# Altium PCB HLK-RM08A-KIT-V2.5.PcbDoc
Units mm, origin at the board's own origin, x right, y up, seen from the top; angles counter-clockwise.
Board outline 90 x 99 mm, 2 copper layers (Top Layer, Bottom Layer); 69 components, 103 nets, 378 pads, 257 vias.
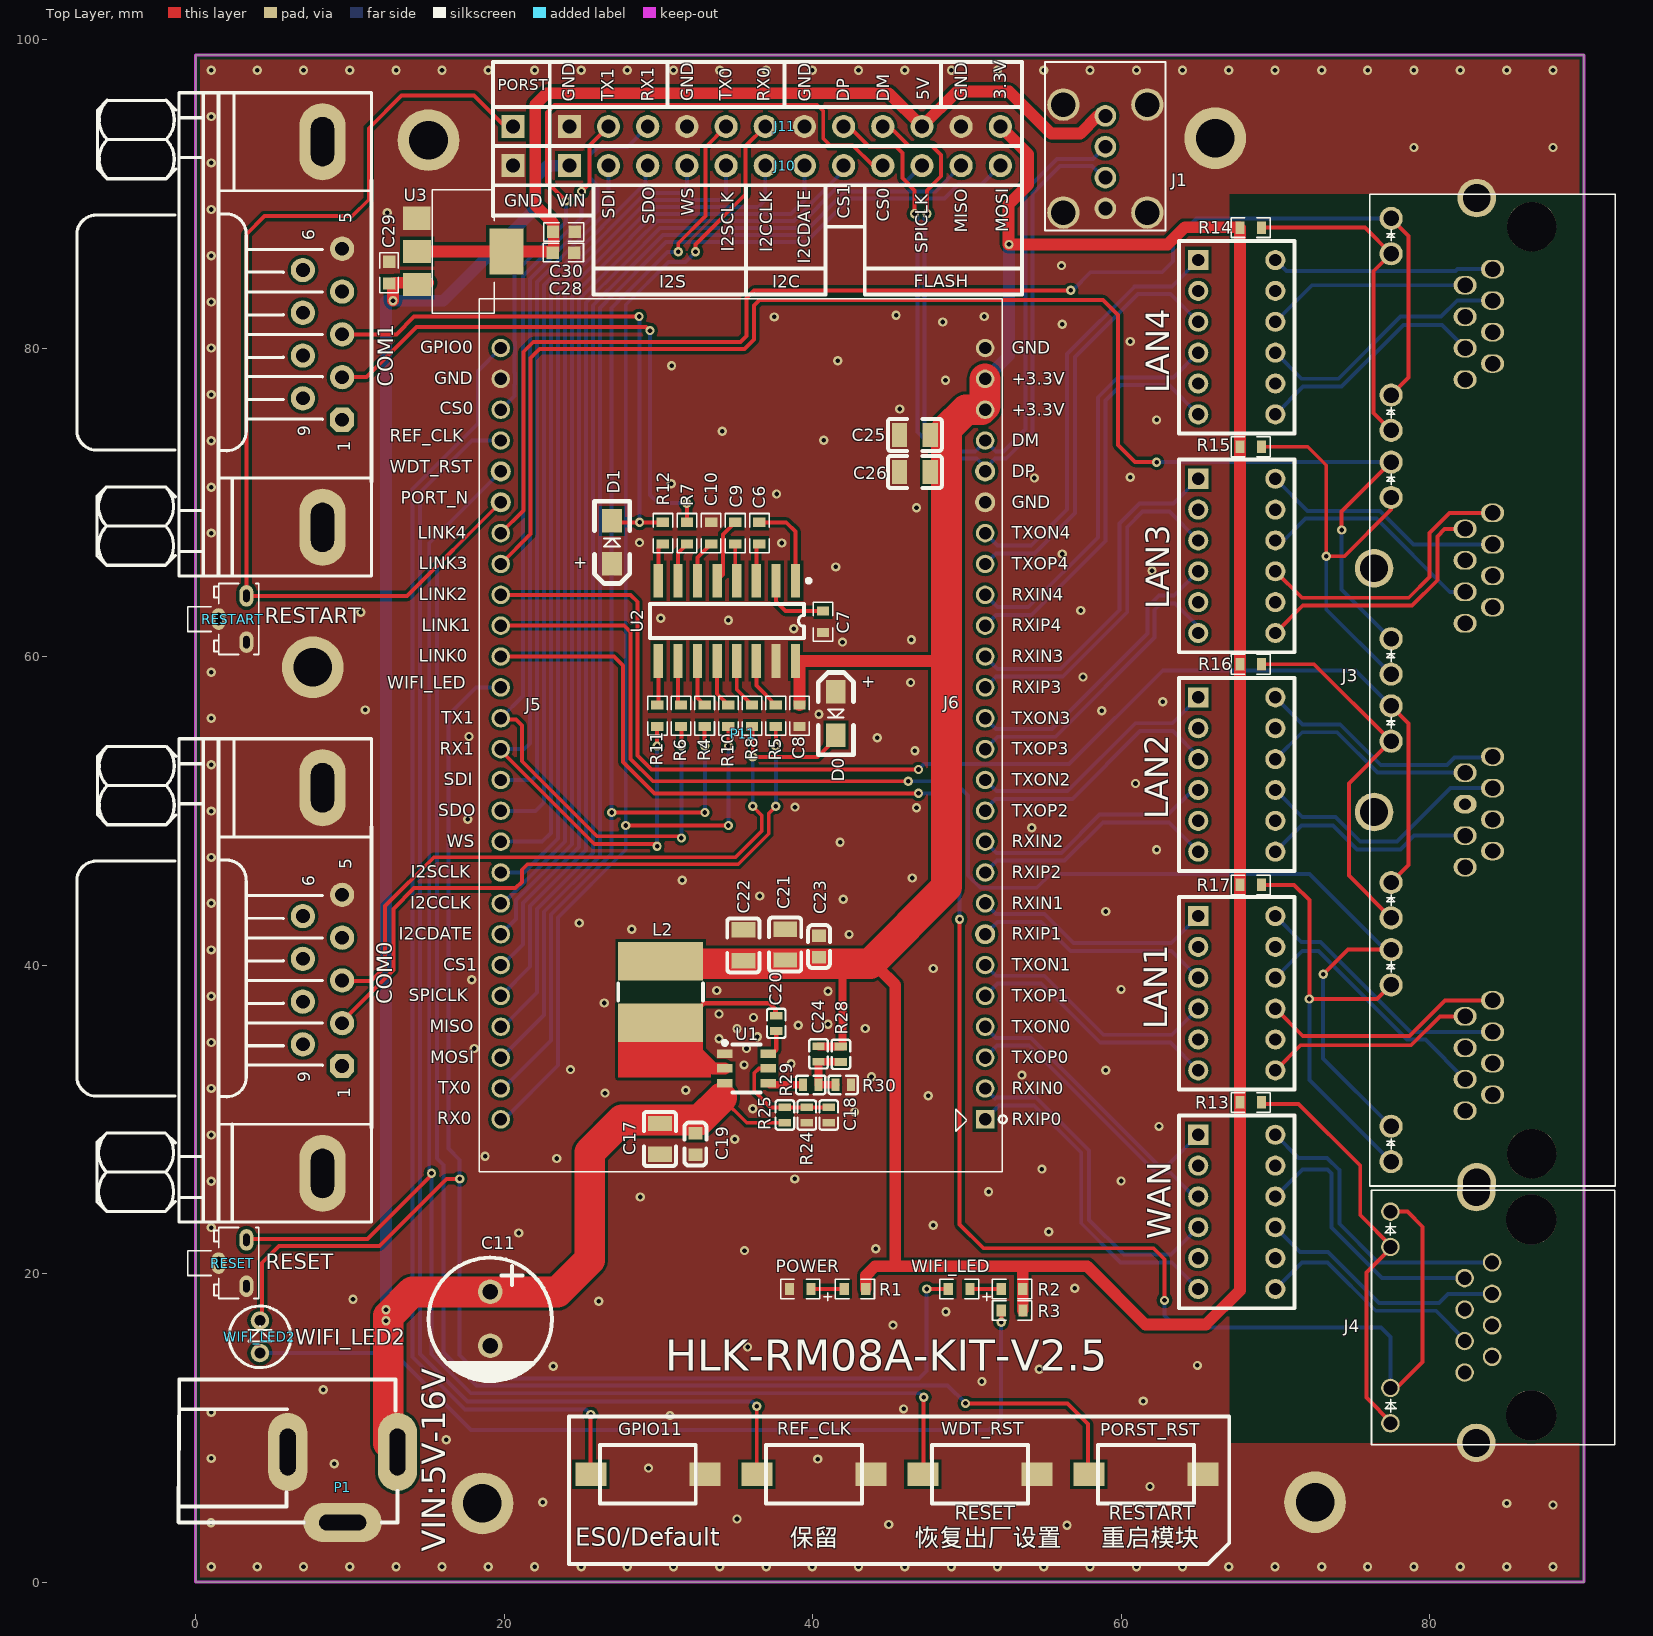
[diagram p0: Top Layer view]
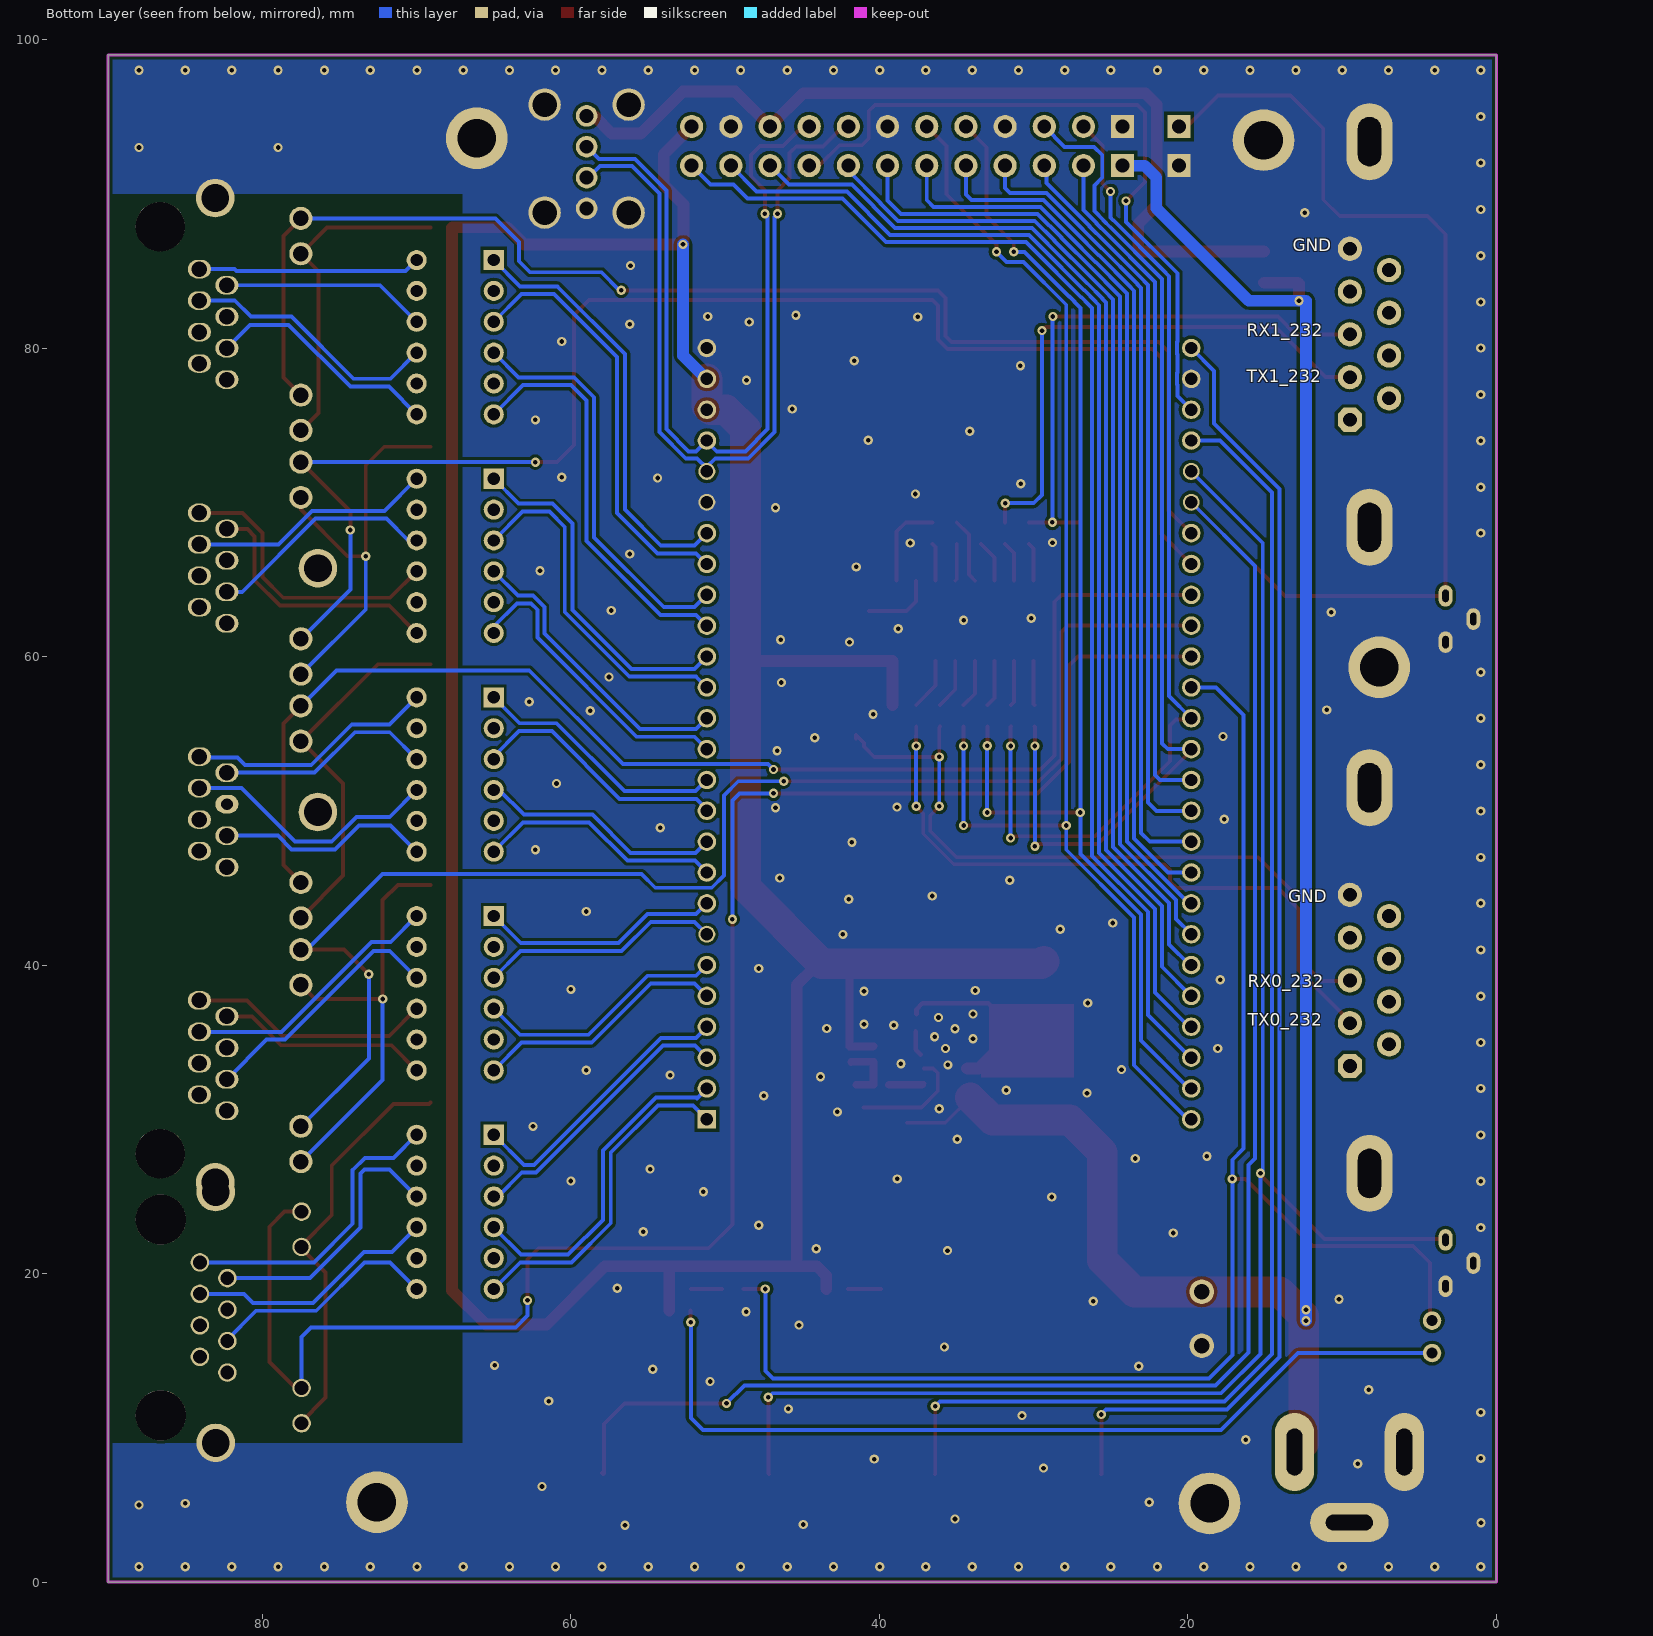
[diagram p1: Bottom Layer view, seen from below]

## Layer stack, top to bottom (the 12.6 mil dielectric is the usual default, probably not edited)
Top Layer: signal copper 0.0356
Dielectric: dielectric 0.32, FR-4, Dk 4.8
Bottom Layer: signal copper 0.0356

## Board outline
0,0 90,0 90,99 0,99

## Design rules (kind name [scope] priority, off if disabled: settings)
Clearance keepout [All] p1: gap=0.2
Clearance router [InNet('GND')] p2: gap=0.2
PlaneConnect [All] p1: planeconnectstyle=Direct reliefexpansion=0.508 reliefentries=4 reliefconductorwidth=0.254 reliefairgap=0.254
PolygonConnect [All] p1: connectstyle=Direct reliefconductorwidth=0.254 reliefentries=4 polygonreliefangle="90 Angle"
RoomDefinition HLK-RM08A-KIT-V2.5 [InComponentClass('HLK-RM08A-KIT-V2.5')] p1: confinementstyle=ConfineIn formatcopy=TRUE lockcomponents=FALSE outline -44.961,-21.523 5.839,-21.523 5.839,3.877 -44.961,3.877
RoutingVias [All] p1: holewidth=0.4 width=0.8 viastyle="Through Hole" minholewidth=0.305 minwidth=0.711 maxholewidth=0.711 maxwidth=1.27
SilkscreenOverComponentPads [IsPad] p1: minsilkscreentomaskgap=0.254
SolderMaskExpansion [All] p1: expansion=0.102
TestPointUsage [All] p1: valid=0 allowmultiple=FALSE
Testpoint [(IsPad And (OnTopLayer Or OnBottomLayer))] p1: side=3 testpointundercomponent=TRUE minsize=1.016 maxsize=2.54 preferedsize=1.524 minholesize=0 maxholesize=1.016 preferedholesize=0.813 testpointgrid=0.025 style=297 order=0-112345678
Width [All] p1: maxlimit=3 minlimit=0.18 preferedwidth=0.2
22 further rules are at their usual default settings.

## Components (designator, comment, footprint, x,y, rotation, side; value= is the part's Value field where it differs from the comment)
C6 "0.1uF/6.3V" 0603#1 36.55,68.001 r90 top
C7 "0.1uF/6.3V" 0603#1 40.671,62.254 r270 top
C8 "0.1uF/6.3V" 0603#1 39.147,56.158 r270 top
C9 "0.1uF/6.3V" 0603#1 34.986,68.001 r270 top
C10 "0.1uF/6.3V" 0603#1 33.422,68.001 r270 top
C11 "470uF 25V" "1000uF 8*12 电解电容" 19.101,17.069 r270 top
C17 "10uF/25V" 0805 30.099,28.727 r90 top
C18 "NC" 0402 41.046,30.277 r90 top
C19 "0.1uF/25V" 0603#2 32.41,28.397 r90 top
C20 "1uF/25V" 0402 37.643,36.22 r270 top
C21 "22uF/6.3V" 0805 38.227,41.326 r270 top
C22 "22uF/6.3V" 0805 35.509,41.275 r270 top
C23 "0.1uF/6.3V" 0603#2 40.411,41.199 r270 top
C24 "NC" 0402 40.386,34.239 r270 top
C25 "22uF/6.3V" 0805 46.634,74.371 r0 top
C26 "22uF/6.3V" 0805 46.634,71.958 r0 top
C28 "0.1uF/6.3V" 0603#3 23.851,86.182 r0 top
C29 "22uF/25V" 0603#3 12.548,84.887 r90 top
C30 "10uF/6.3V" 0603#3 23.876,87.528 r0 top
COM0 "DB9" DB9s 9.5,44.551 r90 top
COM1 "DB9" DB9s 9.5,86.432 r90 top locked
D0 "ZMM5V1" 1005D 41.513,57.701 r270 top
D1 "ZMM5V1" 1005D 27,66 r90 top
GPIO11 "SW-PB" SWITCH 29.185,6.992 r180 top
J1 "USB" USB/4P/P2.0/DIP/R/F/SUA-110VB-B2N 58.979,95.047 r90 top
J3 "RJ45-4" RJ45-4-LED 82.3,46.35 r90 top
J4 "RJ45" RJ45-1-LED 84.048,20.725 r90 top
J10 "2.54*16" HDR1X12 24.232,91.821 r0 top
J11 "2.54*16" HDR1X12 24.232,94.361 r0 top
L2 "6.8uH" "4.7uH SMD,5.8x5.2x4.5mm" 30.15,38.252 r90 top
LAN1 "TF-1016DG" tf-1016dg 65,43.175 r270 top locked
LAN2 "TF-1016DG" tf-1016dg 65,57.35 r270 top locked
LAN3 "TF-1016DG" tf-1016dg 65,71.525 r270 top locked
LAN4 "TF-1016DG" tf-1016dg 65,85.7 r270 top locked
P1 "PWR2.5" POWER_STK1 9.534,8.941 r0 top locked
P11 "7688A" RM08K_52pin 51.186,30 r90 top locked
PORST_RST "SW-PB" SWITCH 61.471,6.992 r180 top
POWER "" 0603LED 39.2,19.001 r180 top
R1 "1K" 0603#1 42.745,19.001 r0 top
R2 "1K" 0603#1 52.931,19.001 r0 top
R3 "1K" 0603#1 52.934,17.602 r0 top
R4 "0R" 0603#1 33.007,56.158 r90 top
R5 "0R" 0603#1 37.612,56.158 r270 top
R6 "0R" 0603#1 31.472,56.158 r90 top
R7 "0R" 0603#1 31.858,68.001 r90 top
R8 "0R" 0603#1 36.077,56.158 r270 top
R10 "0R" 0603#1 34.542,56.158 r90 top
R11 "0R" 0603#1 29.937,56.158 r90 top
R12 "0R" 0603#1 30.293,68.001 r90 top
R13 "1K" 0603#1 68.4,31.1 r180 top
R14 "1K" 0603#1 68.4,87.8 r180 top
R15 "1K" 0603#1 68.4,73.6 r180 top
R16 "1K" 0603#1 68.4,59.5 r180 top
R17 "1K" 0603#1 68.4,45.2 r180 top
R24 "NC" 0402 39.624,30.277 r90 top
R25 "100K" 0402 38.202,30.277 r270 top
R28 "6.2K/1%" 0402 41.834,34.214 r90 top
R29 "1K" 0402 39.878,32.233 r0 top
R30 "2K/1%" 0402 41.986,32.233 r180 top
REF_CLK "SW-PB" SWITCH 39.947,6.992 r180 top
RESET "SW-PB" K5 1.5,20.682 r180 top
RESTART "SW-PB" K5 1.5,62.432 r180 top (schematic designator CS2)
U1 "MP1470" MP1470 35.712,33.299 r270 top
U2 "SP3232" MAX3232 29.495,63.778 r0 top
U3 "AMS1117-5" AMS1117 17.247,86.258 r270 top
WAN "TF-1016DG" tf-1016dg 65,29 r270 top locked
WDT_RST "SW-PB" SWITCH 50.709,6.992 r180 top
WIFI_LED "" 0603LED 49.5,19.001 r180 top
WIFI_LED2 "" LED0.2 4.175,14.85 r90 top

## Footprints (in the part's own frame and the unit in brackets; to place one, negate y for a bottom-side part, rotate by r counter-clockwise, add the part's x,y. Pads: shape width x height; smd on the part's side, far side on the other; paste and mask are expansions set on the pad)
"4.7uH SMD,5.8x5.2x4.5mm" [mm] "SMD,5.8x5.2x4.5mm"
  rect 2.5x5.5 smd: 1(-2,0) 2(2,0)
  silkscreen extent -0.55,-2.75 0.55,2.75
0402 [mm]
  rect 0.5x0.8 smd: 1(-0.5,0) 2(0.5,0)
  silkscreen extent -0.95,-0.6 0.95,0.6
0603#1 [mm]
  rect 0.6x0.8 smd: 1(-0.7,0) 2(0.7,0)
  silkscreen extent -1.27,-0.64 1.27,0.64
0603#2 [mm]
  rect 0.8x0.9 smd: 1(-0.7,0) 2(0.7,0)
  silkscreen extent -1.4,-0.7 1.4,0.72
0603#3 [mm]
  rect 0.8x0.8 smd: 1(-0.7,0) 2(0.7,0)
  silkscreen extent -1.3,-0.6 1.3,0.6
0603LED [mm]
  rect 0.6x0.8 smd: 1(-0.7,0) 2(0.7,0)
  silkscreen extent -2.03,-0.64 1.27,0.76
0805 [mm]
  rect 1x1.55 smd: 1(-1,0) 2(1,0)
  silkscreen extent -1.75,-1.04 1.75,1.04
"1000uF 8*12 电解电容" [mm]
  round 1.6 hole 1: 1(-1.75,0) 2(1.75,0)
  silkscreen extent -3.96,-4 4.04,4
1005D [mil]
  rect 60x50 smd: 1(0,0) 2(110,0)
  silkscreen extent -50,-45 160,45
AMS1117 [mm]
  rect 1.5x1.8 smd: 1(-2.153,-2.905) 2(0.003,-2.884) 3(2.153,-2.884)
  rect 3x2.2 smd: 2(0,2.905)
  silkscreen extent -4,-1.89 4,2.11
DB9s [mil]
  oval 196.85x118.11 hole 59.06 slot 125.98 at 0 deg: 0(273.33,50) 10(-710.83,50)
  oct 62x62 hole 35: 1(-436.67,0)
  round 62 hole 35: 2(-327.5,0) 5(0,0) 6(-54.17,100) 7(-163.33,100) 8(-272.5,100) 9(-381.67,100)
  round 62.01 hole 35: 3(-218.35,0) 4(-109.17,0)
  silkscreen extent -835,-75 398,677
HDR1X12 [mm] "Connector; Header; 16 Position"
  rect 1.5x1.5 hole 0.9: 1(0,0)
  round 1.5 hole 0.9: 2(2.54,0) 3(5.08,0) 4(7.62,0) 5(10.16,0) 6(12.7,0) 7(15.24,0) 8(17.78,0) 9(20.32,0) 10(22.86,0) 11(25.4,0) 12(27.94,0)
  silkscreen extent -1.27,-1.27 29.34,1.27
K5 [mm]
  oval 0.9x1.4 hole 0.4 slot 0.8 at 90 deg: 1(-1.8,1.5) 2(-1.8,-1.5) 3(0,0)
  silkscreen extent -2.6,-2.3 2,2.3
LED0.2 [mm]
  round 1.2 hole 0.7: 1(0,0) 2(2.1,0)
  silkscreen extent -0.95,-2 3.05,2
MAX3232 [mm]
  rect 0.6x2.2 smd: 1(9.398,1.136) 2(8.128,1.136) 3(6.858,1.136) 4(5.588,1.136) 5(4.318,1.136) 6(3.048,1.136) 7(1.778,1.136) 8(0.508,1.136) 9(0.508,-4.064) 10(1.778,-4.064) 11(3.048,-4.064) 12(4.318,-4.064) 13(5.588,-4.064) 14(6.858,-4.064) 15(8.128,-4.064) 16(9.398,-4.064)
  silkscreen extent -0.05,-2.56 10.37,1.26
MP1470 [mm]
  rect 0.55x1 smd: 1(-0.95,-1.4) 2(0,-1.4) 3(0.95,-1.4) 4(0.95,1.4) 5(0,1.4) 6(-0.95,1.4)
  silkscreen extent -1.78,-1.52 1.55,0.9
POWER_STK1 [mil]
  oval 100x200 hole 40 slot 120 at 90 deg: 1(-140,-20) 2(140,-20)
  oval 200x100 hole 40 slot 120 at 0 deg: 3(0,-200)
  silkscreen extent -418,-200 140,165
RJ45-1-LED [mm]
  round 2.5 hole 1.8: 0(4.56,1.02) 13(-11.7,1.02)
  round 1.2 hole 0.89: 1(0,0) 2(-1.02,1.78) 3(-2.04,0) 4(-3.06,1.78) 5(-4.08,0) 6(-5.1,1.78) 7(-6.12,0) 8(-7.14,1.78) 9(3.29,6.59) 10(1,6.59) 11(-8.14,6.59) 12(-10.43,6.59)
  round 3.25 hole 3.25: ""(-9.92,-2.54) ""(2.78,-2.54)
  silkscreen extent -11.81,-7.96 4.67,7.82
RJ45-4-LED [mm]
  round 2.5 hole 1.8: 0(43.37,-0.76) 49(-20.43,-0.76) ""(3.57,5.902) ""(19.37,5.902)
  round 1.5 hole 1: 1(42.051,4.797) 2(39.761,4.797) 11(30.6,4.8) 12(28.31,4.8) 13(26.251,4.797) 14(23.961,4.797) 23(14.8,4.8) 24(12.51,4.8) 25(10.451,4.797) 26(8.161,4.797) 35(-1,4.8) 36(-3.29,4.8) 37(-5.349,4.797) 38(-7.639,4.797) 47(-16.8,4.8) 48(-19.09,4.8)
  oval 1.2x1.5 hole 1: 3(38.761,-1.778) 4(37.72,0) 5(36.721,-1.778) 6(35.68,0) 7(34.681,-1.778) 8(33.64,0) 9(32.641,-1.778) 10(31.6,0) 15(22.961,-1.778) 16(21.92,0) 17(20.921,-1.778) 18(19.88,0) 19(18.881,-1.778) 20(17.84,0) 21(16.841,-1.778) 22(15.8,0) 27(7.161,-1.778) 28(6.12,0) 29(5.121,-1.778) 31(3.081,-1.778) 32(2.04,0) 33(1.041,-1.778) 34(0,0) 39(-8.639,-1.778) 40(-9.68,0) 41(-10.679,-1.778) 42(-11.72,0) 43(-12.719,-1.778) 44(-13.76,0) 45(-14.759,-1.778) 46(-15.8,0)
  oval 1.2x1.5 hole 0.762: 30(4.08,0)
  round 3.2 hole 3.2: ""(-18.58,-4.32) ""(41.52,-4.32)
  silkscreen extent -20.67,-9.72 43.61,6.18
RM08K_52pin [mm]
  rect 1.2x1.2 hole 0.8: 1(0,0)
  round 1.2 hole 0.8: 2(2,0) 3(4,0) 4(6,0) 5(8,0) 6(10,0) 8(14,0) 9(16,0) 10(18,0) 11(20,0) 12(22,0) 13(24,0) 14(26,0) 15(28,0) 16(30,0) 17(32,0) 18(34,0) 19(36,0) 20(38,0) 23(44,0) 24(46,0) 25(48,0) 26(50,0) 27(50,31.4) 28(48,31.4) 29(46,31.4) 30(44,31.4) 33(38,31.4) 34(36,31.4) 35(34,31.4) 36(32,31.4) 37(30,31.4) 38(28,31.4) 39(26,31.4) 40(24,31.4) 41(22,31.4) 42(20,31.4) 43(18,31.4) 44(16,31.4) 45(14,31.4) 46(12,31.4) 47(10,31.4) 48(8,31.4) 49(6,31.4) 50(4,31.4) 51(2,31.4) 52(0,31.4)
  round 1.3 / inner round 1.1 / far side round 1.1 hole 0.8: 7(12,0) 22(42,0)
  round 1.3 / inner round 1.3 / far side round 1.1 hole 0.8: 21(40,0) 31(42,31.4) 32(40,31.4)
  silkscreen extent -3.4,-1.4 53.2,32.8
SWITCH [mm]
  rect 2x1.5 smd: 1(-3.844,0) 2(3.556,0)
  silkscreen extent -3.24,-1.9 2.96,1.9
tf-1016dg [mm]
  rect 1.3x1.3 hole 0.8: 1(0,0)
  round 1.3 hole 0.8: 2(2,0) 3(4,0) 4(6,0) 5(8,0) 6(10,0) 7(10,5) 8(8,5) 9(6,5) 10(4,5) 11(2,5) 12(0,5)
  silkscreen extent -1.25,-1.25 11.25,6.25
USB/4P/P2.0/DIP/R/F/SUA-110VB-B2N [mm]
  round 1.4 hole 0.9: 1(0,0) 2(-2,0) 3(-4,0) 4(-6,0)
  round 2.1 hole 1.6: 5(0.73,2.72) 6(0.73,-2.72) 7(-6.27,2.72) 8(-6.27,-2.72)
  silkscreen extent -7.44,-3.9 3.51,3.9

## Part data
C6 C7 C8 C9 C10: library part Cap, "Capacitor"
C11: library part "1000uF 8*12 电解电容"
C17 C21 C22 C25 C26: library part C0805
C18 C20 C24: library part C0402
C19 C23: library part C0603
C28 C29 C30: library part CAP, "Capacitor"
D0 D1: library part Diode, "Default Diode"
GPIO11 PORST_RST REF_CLK RESET RESTART WDT_RST: "Switch"
J1: library part 2
J4: library part RJ45_1
J10 J11: library part CON16, "Connector"
L2: library part INDUCTOR1
LAN1 LAN2 LAN3 LAN4 P11 WAN: library part Component_1
P1: "Low Voltage Power Supply Connector"
POWER WIFI_LED WIFI_LED2: library part LED
R1 R2 R3 R13 R14 R15 R16 R17: library part Res1, "Resistor"
R4 R5 R6 R7 R8 R10 R11 R12: library part Res2, "Resistor"
R24 R25 R28 R29 R30: library part R0402
U2: library part MAX232ACPE, "+5V Powered, Multi-Channel RS-232 Driver/Receiver"
U3: library part AMS1117-3.3

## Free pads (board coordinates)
  round 4 hole 2.5: 0(7.6,59.3) 1(15.1,93.474) 1(66.1,93.6) 2(72.573,5.182) 3(18.6,5.1)
  rect 1.5x1.5 hole 0.9: 0.9(20.574,91.821) 0.9(20.574,94.361)

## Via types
v1: diameter 0.6, hole 0.3, Top Layer to Bottom Layer, tented both sides, 257 vias

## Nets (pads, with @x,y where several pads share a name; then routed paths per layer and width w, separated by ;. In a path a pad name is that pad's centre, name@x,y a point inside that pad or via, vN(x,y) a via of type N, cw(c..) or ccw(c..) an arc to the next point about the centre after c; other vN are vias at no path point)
+3.3V: C8.1 C21.2 C22.2 C23.2 C24.1 C25.2 C26.2 J11.12 L2.2 P11.24 P11.25 R1.2 R2.2 R3.2 R13.2 R14.2 R15.2 R16.2 R17.2 R28.2 U2.16 | length 230.3
  Top Layer w0.5: C24.1 40.411,34.714 R28.2 ; R28.2@41.935,34.714 41.935,40.081
  Top Layer w0.762: C8.1 39.147,59.714 48.692,59.714 ; R1.2 43.445,19.873 44.046,20.475 47.168,20.475 ; 44.272,39.802 45.364,38.71 45.364,20.475 53.6,20.475 ; J11.12 53.975,92.558 53.975,90.576 52.705,89.306 52.705,86.716 v1(52.73,86.716) 63.017,86.716 64.135,87.833 67.667,87.833 R14.2 R15.2 R16.2 R17.2 R13.2 67.7,18.9 65.5,16.7 61.575,16.7 57.8,20.475 53.6,20.475 ; R3.2@53.631,17.602 R2.2 53.631,20.444 53.6,20.475
  Top Layer w2: L2.2@29.337,40.227 29.482,40.081 43.714,40.081 48.692,45.06 48.692,74.752 49.936,75.997 50.952,75.997 51.186,76.231 P11.25
  Bottom Layer w0.762: P11.25 51.228,78 52.73,79.502 v1(52.73,86.716)
+5: C28.1 C30.1 J1.1 J11.10 U3.2 | length 58.8
  Top Layer w0.762: U3.2@15.074,86.256 23.122,86.256 23.227,86.36 23.227,87.757 23.227,88.051 22.022,89.256 22.022,95.783 22.758,96.52 44.933,96.52 J11.10 49.352,96.622 52.756,96.622 55.474,93.904 57.353,93.904 58.496,95.047 J1.1
+12V_IN: C11.1 C17.2 C19.2 C29.1 J10.1 P1.2 R25.2 U1.3 U3.3 | length 131.6
  Top Layer w0.254: 34.112,31.394 35.73,29.777 R25.2
  Top Layer w0.762: v1(12.8,83.058) 12.8,84.16 12.827,84.187 12.873,84.233 U3.3@15.074,84.233
  Top Layer w2: P1.2 12.497,9.026 12.497,17.247 14.046,18.796 23.47,18.796 25.552,20.879 25.552,27.864 27.646,29.958 32.676,29.958 34.112,31.394
  Bottom Layer w0.762: v1(12.344,16.942) v1(12.344,17.653) 12.344,83.058 v1(12.8,83.058) 16.053,83.058 22.047,89.052 22.047,91.059 22.809,91.821 J10.1
CS0: J10.9 P11.29 | length 46.2
  Top Layer w0.254: v1(24.014,89.535) 22.784,90.765 22.784,95.275 23.266,95.758 40.284,95.758 40.691,95.352 40.691,93.574 41.123,93.142 42.596,93.142 43.917,91.821 J10.9
  Bottom Layer w0.254: P11.29 20.686,76.9 20.686,77.589 20.713,77.616 20.713,78.384 20.686,78.411 20.686,79.589 20.713,79.616 20.713,80.384 20.686,80.411 20.686,84.847 24.014,88.174 v1(24.014,89.535)
CS1: J10.8 P11.47 | length 66.3
  Bottom Layer w0.254: P11.47 19.883,40 21.225,41.342 21.225,44.019 24.851,47.644 24.851,83.148 25.076,83.373 25.076,83.387 26.341,84.652 26.355,84.652 28.651,86.948 28.651,86.963 29.931,88.243 38.796,88.243 39.926,89.372 39.926,89.405 42.012,91.491 J10.8
DM: J1.2 J11.9 P11.23 | length 52.9
  Top Layer w0.254: J11.9 44.983,94.361 46.253,93.091 47.752,93.091 48.336,92.507 48.336,91.135 47.422,90.221 v1(47.422,88.697)
  Bottom Layer w0.254: v1(47.422,88.697) 47.249,88.524 47.249,74.747 48.692,73.304 50.546,73.304 51.186,73.945 P11.23 51.882,73.304 52.368,73.304 53.8,74.737 53.8,90.206 55.844,92.25 58.182,92.25 J1.2
DP: J1.3 J11.8 P11.22 | length 53.7
  Top Layer w0.254: J11.8 42.367,94.361 43.663,93.066 45.39,93.066 45.822,92.634 45.822,91.008 46.609,90.221 v1(46.609,88.697)
  Bottom Layer w0.254: v1(46.609,88.697) 46.795,88.511 46.795,74.559 48.504,72.85 50.644,72.85 51.186,72.309 51.186,72.217 51.819,72.85 52.556,72.85 54.254,74.549 54.254,90.018 56.032,91.796 58.12,91.796 58.869,91.047 J1.3
GND: C7.2 C8.2 C10.1 C11.2 C17.1 C18.1 C19.1 C21.1 C22.1 C23.1 C25.1 C26.1 C28.2 C29.2 C30.2 COM0.0 COM0.5 COM0.10 COM1.0 COM1.5 COM1.10 D0.1 D1.1 GPIO11.1 J1.4 J1.5 J1.6 J1.7 J1.8 J3.0 J4.13 J11.1 J11.4 J11.7 J11.11 P1.1 P1.3 P11.21 P11.26 P11.28 pad.0 pad.0.9@20.574,91.821 pad.1 pad.2 pad.3 PORST_RST.1 POWER.2 R24.1 R30.1 REF_CLK.1 RESET.1 RESET.3 RESTART.1 RESTART.3 U1.1 U2.15 U3.1 WDT_RST.1
  other v1: 1.02,1 4,1 7,1 10,1 13,1 15.98,1 18.98,1 21.98,1 25.003,1 27.983,1 30.983,1 33.983,1 37,1 39.98,1 42.98,1 45.98,1 49,1 51.98,1 54.98,1 57.98,1 61,1 63.98,1 66.98,1 69.98,1 73,1 75.98,1 78.98,1 81.98,1 85,1 88,1 56.49,3.683 44.933,3.734 1,3.855 35.103,4.089 88,5 85,5.1 22.504,5.182 61.874,6.198 29.362,7.391 8.992,7.671 40.335,7.976 1.02,8.02 16.256,9.22 30.759,10.795 1.02,11 45.898,11.227 61.443,11.735 8.28,12.471 50.978,13.005 54.686,13.792 23.19,13.995 64.948,14.046 35.789,15.24 45.212,16.662 48.641,17.526 26.137,18.212 10.211,18.339 56.998,19.05 35.585,21.488 44.094,21.615 20.955,22.631 55.309,22.705 1.02,22.98 47.828,23.139 28.829,24.968 51.41,25.298 1.02,25.98 60,26 38.837,26.137 54.864,26.772 23.419,27.457 18.771,27.61 34.95,28.702 1.02,28.98 62.459,29.54 42.723,30.48 36.119,30.683 47.498,31.521 26.543,31.699 31.775,31.877 1.02,32.003 43.815,32.766 53.569,32.868 59,33.175 24.308,33.223 35.56,33.528 38.608,33.604 18.059,34.595 35.712,34.595 1.02,34.983 33.934,35.23 36.424,35.357 35.103,35.865 43.409,35.89 39.065,36.093 40.996,36.17 36.17,36.601 33.934,36.83 26.492,37.541 1.02,37.983 40.996,38.303 33.782,38.354 60,38.422 17.907,39.04 47.828,39.776 1.02,40.983 42.367,41.986 28.27,42.316 24.867,42.723 59,43.472 1.02,44 41.986,44.272 36.576,44.475 31.547,45.491 46.457,45.644 1.02,46.98 62.301,47.472 41.783,47.955 54.204,48.895 17.653,49.454 1.02,49.98 46.736,50.19 38.862,50.241 60.935,51.765 1.02,52.98 46.634,53.899 44.196,54.737 17.729,54.813 1.02,56 40.411,56.261 58.75,56.49 11,56.539 62.7,57.066 46.355,58.318 57.531,58.674 1.02,58.98 41.935,60.935 46.406,61.087 38.786,61.798 34.544,62.357 30.15,62.484 10.713,62.876 57.388,62.984 62.001,65.557 41.504,65.811 56.185,66.65 37.998,67.361 28.778,67.386 1.02,68 46.736,69.647 37.668,70.536 1.02,70.98 30.836,71.196 54.381,71.577 60.6,71.62 1.02,73.98 40.716,74.016 34.138,74.6 62.301,75.34 45.644,76.048 1.02,76.98 48.616,77.902 30.861,78.842 41.631,79.172 1.02,80 60.6,80.422 56.185,81.534 48.438,81.686 37.516,82.017 51.13,82.042 45.415,82.118 1.02,82.98 56.134,85.344 1.02,85.98 12.434,88.766 1.02,88.98 1.02,92 78.98,93 88,93 1.02,95 1.02,98 4,98 7,98 10,98 13,98 15.98,98 18.98,98 21.98,98 25.003,98 27.983,98 30.983,98 33.983,98 37,98 39.98,98 42.98,98 45.98,98 49,98 51.98,98 54.98,98 57.98,98 61,98 63.98,98 66.98,98 69.98,98 73,98 75.98,98 78.98,98 81.98,98 85,98 88,98
GPIO: GPIO11.2 P11.27 | length 84.8
  Top Layer w0.254: v1(25.613,10.864) 25.613,7.008 GPIO11.2
  Bottom Layer w0.254: P11.27 18.298,78.512 18.298,75.098 14.055,70.855 14.055,14.596 17.475,11.176 25.324,11.176 25.613,10.887 v1@25.613,10.836
I2CCLK: J10.6 P11.45 | length 59.1
  Bottom Layer w0.254: P11.45 19.922,44 23.943,48.021 23.943,83.524 24.168,83.749 24.168,83.763 25.965,85.56 25.979,85.56 27.743,87.324 27.743,87.339 29.555,89.151 36.5,89.151 36.932,89.583 J10.6
I2CDATE: J10.7 P11.46 | length 63.2
  Bottom Layer w0.254: P11.46 20.771,42.985 20.771,44.207 24.397,47.833 24.397,83.336 24.622,83.561 24.622,83.575 26.153,85.106 26.167,85.106 28.197,87.136 28.197,87.151 29.743,88.697 38.608,88.697 39.472,89.56 J10.7
I2SCLK: J10.5 P11.44 | length 55.7
  Bottom Layer w0.254: P11.44 21.28,46 23.489,48.209 23.489,83.712 23.714,83.937 23.714,83.951 25.777,86.014 25.791,86.014 27.289,87.512 27.289,87.527 29.367,89.605 34.036,89.605 34.392,89.96 34.392,91.364 34.163,91.592 J10.5
L0: J4.10 J4.12 R13.1 | length 27
  Top Layer w0.254: R13.1 69.2,31 71.5,31 75.5,27 75.5,23.785 77.56,21.725 75.895,20.06 75.895,11.96 J4.12@77.56,10.295
L1: J3.38 J3.48 R17.1 | length 28.3
  Top Layer w0.254: R17.1 71.217,45.2 72.2,44.217 v1(72.2,37.8) 76.592,37.8 J3.38
  Bottom Layer w0.254: v1(72.2,37.8) 72.2,32.56 J3.48
L2: J3.26 J3.36 R16.1 | length 24.2
  Top Layer w0.254: R16.1 72.514,59.5 J3.26 74.767,51.775 74.767,45.793 J3.36
L3: J3.14 J3.24 R15.1 | length 26.2
  Top Layer w0.254: R15.1 72.1,73.6 73.3,72.4 v1(73.3,66.5) 74.475,66.5 77.503,69.528 J3.14
  Bottom Layer w0.254: v1(73.3,66.5) 73.3,63.06 J3.24
L4: J3.2 J3.12 R14.1 | length 21.5
  Top Layer w0.254: R14.1 75.814,87.8 J3.2 76.369,84.977 76.369,75.791 J3.12
LINK0: J4.9 J4.11 P11.37 | length 115
  Top Layer w0.254: P11.37 27.122,60 27.711,59.411 27.711,53.162 29.743,51.13 v1(46.863,51.13) ; v1(49.53,42.977) 49.53,23.19 51.079,21.641 62.103,21.641 62.814,20.93 v1(62.814,18.263) ; J4.11@77.56,12.585 77.846,12.585 79.541,14.28 79.541,23.034 78.56,24.015 J4.9@77.56,24.015
  Bottom Layer w0.254: v1(46.863,51.13) 49.073,51.13 49.53,50.673 v1(49.53,42.977) ; v1(62.814,18.263) 62.814,17.272 63.576,16.51 76.835,16.51 77.458,15.887 J4.11
LINK1: J3.37 J3.47 P11.36 | length 91.8
  Top Layer w0.254: P11.36 27.789,62 28.194,61.595 28.194,53.365 29.642,51.918 v1(46.203,51.918) ; v1(73.1,39.4) 74.701,41.001 J3.37
  Bottom Layer w0.254: v1(46.203,51.918) 49.149,51.918 50.063,51.003 50.063,45.812 50.866,45.009 54.534,45.009 55.425,45.9 72.218,45.9 77.117,41.001 J3.37 ; v1(73.1,39.4) 73.1,33.95 J3.47
LINK2: J3.25 J3.35 P11.35 | length 84.2
  Top Layer w0.254: P11.35 28.202,64 28.651,63.551 28.651,53.594 29.566,52.68 v1(46.863,52.68) ; J3.35 78.634,46.484 78.634,55.67 J3.25
  Bottom Layer w0.254: v1(46.863,52.68) 47.219,53.035 56.635,53.035 62.7,59.1 75.204,59.1 J3.25
LINK3: J3.13 J3.23 P11.34 | length 96.2
  Top Layer w0.254: P11.34 21.717,67.931 21.717,79.35 22.301,79.934 35.585,79.934 36.195,80.543 36.195,82.753 36.551,83.109 58.826,83.109 59.792,82.144 59.792,73.711 60.901,72.601 v1(62.301,72.601) ; v1(74.3,68.2) 74.3,69.398 J3.13
  Bottom Layer w0.254: v1(62.301,72.601) J3.13 ; v1(74.3,68.2) 74.3,64.35 J3.23
LINK4: J3.1 J3.11 P11.33 | length 86.8
  Top Layer w0.254: P11.33 21.26,69.474 21.26,79.756 21.895,80.391 35.331,80.391 35.717,80.777 35.717,83.241 36.213,83.736 v1(56.728,83.736) ; J3.11 78.634,78.084 78.634,87.27 J3.1
  Bottom Layer w0.254: v1(56.728,83.736) 56.838,83.736 58.014,84.912 62.662,84.912 63.373,85.623 63.373,86.877 64.897,88.401 J3.1
MISO: J10.11 P11.49 | length 76.9
  Bottom Layer w0.254: P11.49 19.922,36 22.133,38.211 22.133,43.643 25.759,47.268 25.759,82.772 25.984,82.997 25.984,83.011 26.717,83.744 26.731,83.744 29.559,86.572 29.559,86.587 30.307,87.335 39.303,87.335 42.113,90.145 47.955,90.145 J10.11@49.606,91.796
MOSI: J10.12 P11.50 | length 81
  Bottom Layer w0.254: P11.50 19.827,34 22.587,36.76 22.587,43.455 26.213,47.08 26.213,82.584 26.438,82.809 26.438,82.823 26.905,83.29 26.919,83.29 30.013,86.384 30.013,86.399 30.495,86.881 39.586,86.881 42.396,89.691 48.543,89.691 49.454,90.602 50.952,90.602 J10.12@52.146,91.796
NetC6_1: C6.1 U2.3 | length 2.5
  Top Layer w0.254: U2.3 36.353,67.103 C6.1
NetC6_2: C6.2 U2.1 | length 5.8
  Top Layer w0.254: C6.2 38.294,68.701 38.893,68.102 U2.1
NetC7_1: C7.1 U2.2 | length 4.6
  Top Layer w0.254: U2.2 37.623,63.573 38.242,62.954 C7.1
NetC9_1: C9.1 U2.5 | length 4.3
  Top Layer w0.254: U2.5 34.205,65.306 34.205,67.92 C9.1
NetC9_2: C9.2 U2.4 | length 2.4
  Top Layer w0.254: C9.2 34.986,65.011 U2.4
NetC10_2: C10.2 U2.6 | length 2.8
  Top Layer w0.254: U2.6 32.543,66.422 C10.2
NetC18_2: C18.2 R24.2 R25.1 U1.5 | length 7.4
  Top Layer w0.254: U1.5 36.525,33.299 36.22,32.995 36.22,31.826 37.27,30.777 R25.1 R24.2 C18.2
NetC20_1: C20.1 L2.1 U1.2 | length 16.2
  Top Layer w0.3: L2.1@29.337,36.227 30.131,36.227 30.632,36.728 32.156,36.728 32.944,37.516 37.211,37.516 37.592,37.135 C20.1@37.592,36.822
  Top Layer w0.8: L2.1@28.55,36.252 30.6,36.252 33.553,33.299 U1.2
NetC20_2: C20.2 U1.6 | length 1.7
  Top Layer w0.3: U1.6@37.313,34.188 37.643,34.519 C20.2
NetC24_2: C24.2 R28.1 R29.2 R30.2 | length 4.1
  Top Layer w0.3: R28.1@41.816,33.696 R28.1
  Top Layer w0.5: R30.2 R29.2 40.386,32.24 C24.2 41.808,33.739 R28.1
NetJ3_3: J3.3 LAN4.12 | length 14.4
  Bottom Layer w0.254: LAN4.12 70.72,84.98 81.673,84.98 81.804,85.111 J3.3
NetJ3_4: J3.4 LAN4.10 | length 13.3
  Bottom Layer w0.254: LAN4.10 72.37,84.07 J3.4
NetJ3_5: J3.5 LAN4.9 | length 16.9
  Bottom Layer w0.254: LAN4.9 71.692,78.008 74.09,78.008 78.112,82.03 80.747,82.03 81.788,83.071 J3.5
NetJ3_8: J3.8 LAN4.7 | length 15.3
  Bottom Layer w0.254: LAN4.7 71.8,77.5 74.3,77.5 78.3,81.5 80.79,81.5 J3.8
NetJ3_15: J3.15 LAN3.9 | length 18.7
  Top Layer w0.254: LAN3.9 71.717,63.808 78.647,63.808 79.992,65.153 79.992,68.004 81.299,69.311 J3.15
NetJ3_16: J3.16 LAN3.7 | length 16.8
  Top Layer w0.254: LAN3.7 71.775,63.3 78.857,63.3 80.5,64.943 80.5,67.794 80.976,68.27 J3.16
NetJ3_17: J3.17 LAN3.12 | length 15.8
  Bottom Layer w0.254: LAN3.12 72.08,69.445 76.77,69.445 78.944,67.271 J3.17
NetJ3_20: J3.20 LAN3.10 | length 14.9
  Bottom Layer w0.254: LAN3.10 70.542,67.525 71.954,68.937 76.56,68.937 81.307,64.19 J3.20
NetJ3_27: J3.27 LAN2.12 | length 16.1
  Bottom Layer w0.254: LAN2.12 71.75,55.6 74.208,55.6 76.83,52.978 81.128,52.978 81.601,53.451 84.018,53.451 J3.27
NetJ3_28: J3.28 LAN2.10 | length 14.1
  Bottom Layer w0.254: LAN2.10 71.742,55.092 73.998,55.092 76.62,52.47 J3.28
NetJ3_29: J3.29 LAN2.9 | length 16.9
  Bottom Layer w0.254: LAN2.9 71.742,49.608 73.892,49.608 75.5,48 77.892,48 81.363,51.471 J3.29
NetJ3_32: J3.32 LAN2.7 | length 14
  Bottom Layer w0.254: LAN2.7 71.684,49.034 73.748,49.034 75.29,47.492 78.102,47.492 79,48.39 J3.32
NetJ3_39: J3.39 LAN1.9 | length 15.8
  Top Layer w0.254: LAN1.9 71.775,35.4 78.682,35.4 80.993,37.711 J3.39
NetJ3_40: J3.40 LAN1.7 | length 13.7
  Top Layer w0.254: LAN1.7 71.625,34.8 78.8,34.8 80.67,36.67 J3.40
NetJ3_41: J3.41 LAN1.12 | length 17.2
  Bottom Layer w0.254: LAN1.12 71.675,41.5 72.918,41.5 78.747,35.671 J3.41
NetJ3_44: J3.44 LAN1.10 | length 16.5
  Bottom Layer w0.254: LAN1.10 71.742,40.917 72.783,40.917 78.537,35.163 79.727,35.163 J3.44
NetJ4_1: J4.1 WAN.12 | length 19.6
  Bottom Layer w0.254: WAN.12 71.5,27.5 73.35,27.5 74.144,26.707 74.144,23.24 76.659,20.725 J4.1@84.15,20.725
NetJ4_2: J4.2 WAN.10 | length 18.1
  Bottom Layer w0.254: WAN.10 71.752,26.752 73.379,26.752 73.636,26.496 73.636,22.98 76.911,19.705 J4.2@82.37,19.705
NetJ4_3: J4.3 WAN.9 | length 16.4
  Bottom Layer w0.254: WAN.9 71.6,21.4 73.418,21.4 76.718,18.1 80.6,18.1 81.185,18.685 J4.3@84.15,18.685
NetJ4_6: J4.6 WAN.7 | length 15.2
  Bottom Layer w0.254: WAN.7 71.725,20.725 73.375,20.725 76.508,17.592 80.403,17.592 J4.6@82.37,15.625
NETL: J3.49 J4.0
NetPOWER_1: POWER.1 R1.1 | length 2.1
  Top Layer w0.254: POWER.1 R1.1
NetR2_1: R2.1 WIFI_LED.1 | length 2
  Top Layer w0.254: WIFI_LED.1 R2.1
NetR3_1: R3.1 WIFI_LED2.1 | length 57.4
  Top Layer w0.254: v1(52.222,16.84) 52.234,16.851 R3.1
  Bottom Layer w0.254: WIFI_LED2.1 12.861,14.85 17.856,9.855 51.435,9.855 52.222,10.643 v1(52.222,16.84)
NetR4_2: R4.2 U2.11 | length 3
  Top Layer w0.254: U2.11 32.543,57.322 R4.2
NetR5_1: R5.1 U2.14 | length 3.4
  Top Layer w0.254: U2.14 36.353,58.117 R5.1
NetR6_2: R6.2 U2.10 | length 2.9
  Top Layer w0.254: U2.10 31.273,57.057 R6.2
NetR7_1: R7.1 U2.7 | length 2.6
  Top Layer w0.254: U2.7 31.273,66.716 R7.1
NetR8_1: R8.1 U2.13 | length 3.3
  Top Layer w0.254: U2.13 35.083,57.852 R8.1
NetR10_2: R10.2 U2.12 | length 3.2
  Top Layer w0.254: U2.12 33.813,57.587 R10.2
NetR11_2: R11.2 U2.9 | length 2.9
  Top Layer w0.254: R11.2 30.003,56.924 U2.9
NetR12_1: R12.1 U2.8 | length 2.5
  Top Layer w0.254: U2.8 30.003,67.01 R12.1
NetR29_1: R29.1 U1.4 | length 2.3
  Top Layer w0.3: U1.4 U1.4@37.229,32.233
  Top Layer w0.5: U1.4@37.229,32.233 R29.1
PORST_RST: P11.32 pad.0.9@20.574,94.361 PORST_RST.2 RESTART.2 | length 170.6
  Top Layer w0.254: P11.32 13.718,63.932 RESTART.2 3.3,87.374 4.47,88.544 10.16,88.544 11.227,89.611 11.227,94.234 13.36,96.368 18.059,96.368 pad.0.9@20.066,94.361 ; v1(49.911,11.582) 56.515,11.582 57.861,10.236 57.861,7.045 PORST_RST.2 PORST_RST.2@57.998,7.075
  Bottom Layer w0.254: P11.32 15.656,65.87 15.656,27.473 16.078,27.051 16.078,14.884 18.212,12.751 48.757,12.751 v1@49.911,11.597
REF_CLK: P11.30 REF_CLK.2 | length 90.1
  Top Layer w0.254: v1(36.382,11.395) 36.382,7 REF_CLK.2
  Bottom Layer w0.254: P11.30 17.919,74 14.563,70.645 14.563,14.774 17.628,11.709 36.068,11.709 v1(36.382,11.395)
RX0: J11.6 P11.52 R10.1 | length 85.3
  Top Layer w0.254: v1(27.889,49.047) v1(34.542,49.047) ; v1(32.41,86.233) 32.41,86.716 35.662,89.967 35.662,93.091 J11.6 ; v1(34.542,54.204) R10.1
  Bottom Layer w0.254: P11.52 19.992,30 23.495,33.503 23.495,43.078 27.889,47.473 v1(27.889,49.047) 27.889,82.804 30.658,85.573 31.75,85.573 v1(32.41,86.233) ; v1(34.542,49.047) v1(34.542,54.204)
RX0_232: COM0.3 D0.2 R8.2 | length 46.9
  Top Layer w0.254: COM0.3 9.542,38.964 11.379,38.964 12.294,39.878 12.294,43.815 15.465,46.987 34.991,46.987 36.703,48.699 36.703,49.708 v1(36.119,50.292) ; R8.2 36.119,55.416 v1(36.119,53.492) 40.335,53.492 41.005,54.162 41.005,54.399 D0.2 D0.2@41.513,54.67
  Bottom Layer w0.254: v1(36.119,50.292) v1(36.119,53.492)
RX1: J11.3 P11.40 R11.1 | length 67.3
  Top Layer w0.254: P11.40 19.786,53.915 25.847,47.854 29.778,47.854 29.931,47.701 v1(29.921,47.701) ; v1(29.921,54.204) 29.921,55.442 R11.1
  Bottom Layer w0.254: P11.40 21.31,54 21.673,54.363 21.673,84.464 21.898,84.689 21.898,84.704 25.024,87.83 25.039,87.83 25.473,88.264 25.473,88.279 26.064,88.871 26.064,90.547 25.552,91.059 25.552,92.507 26.086,93.04 27.991,93.04 J11.3 ; v1(29.921,47.701) 29.921,48.346 v1(29.921,54.204)
RX1_232: COM1.3 D1.2 R12.2 | length 36.4
  Top Layer w0.254: COM1.3 13.017,80.886 14.161,82.03 v1@28.753,82.03 ; D1.2 27.093,68.701 v1(28.788,68.701) R12.2
  Bottom Layer w0.254: v1(28.753,82.042) 28.778,82.017 28.778,68.71 v1(28.788,68.701)
RXIN0: P11.2 WAN.4 | length 21.7
  Bottom Layer w0.254: P11.2 51.827,31.359 51.876,31.408 54.495,31.408 57.925,27.978 57.925,23.475 60.175,21.225 63.225,21.225 WAN.4
RXIN1: LAN1.1 P11.8 | length 15.6
  Bottom Layer w0.254: P11.8 51.878,43.308 55.035,43.308 56.918,41.425 63.25,41.425 LAN1.1
RXIN2: LAN2.4 P11.10 | length 15.8
  Bottom Layer w0.254: P11.10 51.911,47.275 56.132,47.275 58.607,49.75 63.052,49.75 64.652,51.35 LAN2.4
RXIN3: LAN3.1 P11.16 | length 22.5
  Bottom Layer w0.254: P11.16 51.986,59.2 56.069,59.2 59.892,63.023 59.892,68.61 61.19,69.908 63.383,69.908 LAN3.1
RXIN4: LAN4.4 P11.18 | length 26.3
  Bottom Layer w0.254: P11.18 51.986,63.2 53.982,63.2 58.492,67.71 58.492,76.81 59.782,78.1 63.4,78.1 LAN4.4
RXIP0: P11.1 WAN.6 | length 21.8
  Bottom Layer w0.254: P11.1 52.086,30.9 54.361,30.9 57.417,27.844 57.417,23.265 59.965,20.717 63.283,20.717 WAN.6
RXIP1: LAN1.3 P11.7 | length 15.6
  Bottom Layer w0.254: P11.7 51.986,42.8 54.825,42.8 56.708,40.917 63.258,40.917 LAN1.3
RXIP2: LAN2.6 P11.9 | length 15.9
  Bottom Layer w0.254: P11.9 51.953,46.767 56.342,46.767 58.817,49.242 63.108,49.242 LAN2.6
RXIP3: LAN3.3 P11.15 | length 22.5
  Bottom Layer w0.254: P11.15 51.878,58.692 56.203,58.692 60.4,62.889 60.4,68.4 61.4,69.4 63.125,69.4 LAN3.3
RXIP4: LAN4.6 P11.17 | length 26.4
  Bottom Layer w0.254: P11.17 51.878,62.692 54.192,62.692 59,67.5 59,76.6 59.992,77.592 63.108,77.592 LAN4.6
SDI: J10.2 P11.41 | length 43.9
  Bottom Layer w0.254: P11.41 21.819,52 22.127,52.308 22.127,84.276 22.352,84.501 22.352,84.516 25.212,87.376 25.227,87.376 25.927,88.076 25.927,88.091 26.772,88.936 J10.2
SDO: J10.3 P11.42 | length 47.1
  Bottom Layer w0.254: P11.42 22.035,50 22.581,50.546 22.581,84.088 22.806,84.313 22.806,84.328 25.4,86.922 25.415,86.922 26.381,87.888 26.381,87.903 29.168,90.69 29.168,91.677 J10.3
SPICLK: J10.10 P11.48 | length 72.7
  Bottom Layer w0.254: P11.48 19.788,38 21.679,39.891 21.679,43.831 25.305,47.456 25.305,82.96 25.53,83.185 25.53,83.199 26.529,84.198 26.543,84.198 29.105,86.76 29.105,86.775 30.119,87.789 38.984,87.789 40.38,89.184 40.38,89.217 41.765,90.602 45.872,90.602 J10.10@47.066,91.796
TX0: J11.5 P11.51 R4.1 | length 80.6
  Top Layer w0.254: v1(26.975,49.886) v1(33.02,49.886) ; v1(31.293,86.233) 31.293,86.792 33.045,88.544 33.045,93.015 J11.5 ; v1@32.969,54.178 v1(33.007,54.216) R4.1
  Bottom Layer w0.254: P11.51 19.986,32.2 20.135,32.2 23.041,35.106 23.041,43.266 26.975,47.2 v1(26.975,49.886) 26.975,82.601 27.352,82.978 27.352,83.026 27.667,83.341 27.715,83.341 30.607,86.233 v1(31.293,86.233) ; v1(33.007,54.216) 33.013,54.209 33.013,49.892 v1(33.02,49.886)
TX0_232: COM0.2 R5.2 | length 42.7
  Top Layer w0.254: COM0.2 9.5,36.348 12.827,39.675 12.827,43.637 14.173,44.983 20.752,44.983 21.158,45.39 21.158,46.177 21.514,46.533 35.179,46.533 37.16,48.514 37.16,49.835 v1(37.617,50.292) ; R5.2 37.612,54.846 37.617,54.84 v1(37.617,54.204)
  Bottom Layer w0.254: v1(37.617,50.292) v1(37.617,54.204)
TX1: J11.2 P11.39 R6.1 | length 64.8
  Top Layer w0.254: P11.39 19.871,55.915 20.767,55.915 21.158,55.524 21.158,53.213 26.023,48.348 31.382,48.348 v1(31.496,48.235) ; v1(25.019,90.145) 25.527,90.653 25.527,93.116 J11.2 ; R6.1 31.496,55.434 v1(31.496,54.204)
  Bottom Layer w0.254: P11.39 21.219,57.433 21.219,84.652 21.444,84.877 21.444,84.892 24.836,88.284 24.851,88.284 25.019,88.452 v1(25.019,90.145) ; v1(31.496,48.235) v1(31.496,54.204)
TX1_232: COM1.2 R7.2 | length 35.9
  Top Layer w0.254: COM1.2 11.082,78.113 14.326,81.356 29.213,81.356 v1@29.464,81.105 ; v1(31.836,69.944) 31.858,69.922 R7.2
  Bottom Layer w0.254: v1(29.464,81.128) 29.464,70.474 29.994,69.944 v1(31.836,69.944)
TXON0: P11.4 WAN.1 | length 18.3
  Bottom Layer w0.254: P11.4 51.903,35.283 54.157,35.283 62.39,27.05 63.05,27.05 WAN.1
TXON1: LAN1.4 P11.6 | length 16.4
  Bottom Layer w0.254: P11.6 51.878,39.308 55.035,39.308 58.86,35.483 63.308,35.483 LAN1.4
TXON2: LAN2.1 P11.12 | length 16.6
  Bottom Layer w0.254: P11.12 51.911,51.275 56.533,51.275 60.933,55.675 63.325,55.675 LAN2.1
TXON3: LAN3.4 P11.14 | length 19.3
  Bottom Layer w0.254: P11.14 51.878,55.308 55.533,55.308 61.722,61.497 61.722,63.221 62.459,63.958 63.433,63.958 LAN3.4
TXON4: LAN4.1 P11.20 | length 27.7
  Bottom Layer w0.254: P11.20 51.986,67.2 54.175,67.2 56.5,69.525 56.5,79.618 60.882,84 63.3,84 LAN4.1
TXOP0: P11.3 WAN.3 | length 18.2
  Bottom Layer w0.254: P11.3 51.961,34.775 54.023,34.775 62.256,26.542 63.183,26.542 64.725,25 WAN.3
TXOP1: LAN1.6 P11.5 | length 16.5
  Bottom Layer w0.254: P11.5 51.986,38.8 54.825,38.8 58.65,34.975 63.2,34.975 LAN1.6
TXOP2: LAN2.3 P11.11 | length 16.9
  Bottom Layer w0.254: P11.11 51.186,50.086 51.867,50.767 56.838,50.767 61.238,55.167 63.358,55.167 65,53.525 LAN2.3
TXOP3: LAN3.6 P11.13 | length 19.8
  Bottom Layer w0.254: P11.13 51.986,54.8 55.743,54.8 62.176,61.233 62.176,63.033 62.593,63.45 63.5,63.45 65,61.95 LAN3.6
TXOP4: LAN4.3 P11.19 | length 27.7
  Bottom Layer w0.254: P11.19 51.878,66.692 54.385,66.692 57.008,69.315 57.008,79.408 61.092,83.492 63.208,83.492 LAN4.3
WDT_RST: P11.31 RESET.2 WDT_RST.2 | length 111.1
  Top Layer w0.254: RESET.2 3.366,22.247 11.147,22.247 15.3,26.4 v1(15.3,26.5) ; WDT_RST.2 47.203,7.042 v1(47.203,11.979)
  Bottom Layer w0.254: v1@15.3,26.496 v1(15.3,26.5) ; P11.31 15.148,67.362 15.148,26.652 v1(15.3,26.5) ; v1(47.203,11.979) 46.939,12.243 17.856,12.243 15.3,14.799 v1(15.3,26.5)
WIFI_LED: P11.38 WIFI_LED2.2 WIFI_LED.2 | length 102.6
  Top Layer w0.254: WIFI_LED2.2 4.319,17.094 4.319,20.702 5.41,21.793 9.525,21.793 11.913,21.793 16.256,26.137 v1(17.12,26.137) ; v1@47.401,19.001 WIFI_LED.2
  Bottom Layer w0.254: P11.38 18.19,58 16.392,56.203 16.392,28.108 17.12,27.381 v1(17.12,26.137) 17.12,14.732 18.647,13.205 46.911,13.205 47.396,13.691 v1@47.396,18.996
  other v1: 47.4,19
WS: J10.4 P11.43 | length 51.8
  Bottom Layer w0.254: P11.43 22.473,48 23.035,48.562 23.035,83.9 23.26,84.125 23.26,84.139 25.588,86.468 25.603,86.468 26.835,87.7 26.835,87.715 29.179,90.059 31.547,90.059 31.852,90.364 J10.4
pads on no net: COM0.1 COM0.4 COM0.6 COM0.7 COM0.8 COM0.9 COM1.1 COM1.4 COM1.6 COM1.7 COM1.8 COM1.9 J3. J3.6 J3.7 J3.9 J3.10 J3.18 J3.19 J3.21 J3.22 J3.30 J3.31 J3.33 J3.34 J3.42 J3.43 J3.45 J3.46 J4. J4.4 J4.5 J4.7 J4.8 LAN1.2 LAN1.5 LAN1.8 LAN1.11 LAN2.2 LAN2.5 LAN2.8 LAN2.11 LAN3.2 LAN3.5 LAN3.8 LAN3.11 LAN4.2 LAN4.5 LAN4.8 LAN4.11 WAN.2 WAN.5 WAN.8 WAN.11

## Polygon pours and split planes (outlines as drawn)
GND on Top Layer "Top Layer-No Net" (solid, pour order 1004): 0,99 90,99 90,90 67,90 67,9.045 66.98,9.025 67.005,9 90,9 90,0 0,0
GND on Bottom Layer "Top Layer-No Net" (solid, pour order 1003): 0,99 90,99 90,90 67,90 67,9.045 66.98,9.025 67.005,9 90,9 90,0 0,0

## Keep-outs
Keep-Out Layer:
  the board outline again, w0.203

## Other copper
Top Layer:
  rectangle net NetC20_1: 27.381,32.715 32.896,37.49
  rectangle net NetC20_1: 31.267,32.715 33.426,33.774
  pour cut-out: 27.203,41.123 27.203,36.398 27.178,36.373 27.534,36.017 32.715,36.017 33.122,36.424 33.122,41.097 33.071,41.148 27.229,41.148

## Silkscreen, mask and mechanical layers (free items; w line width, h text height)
Top Overlay:
  lines w0.102: 49.971,29.914 49.285,29.228 49.285,30.65 49.971,29.964
  lines w0.254: 19.279,93.091 22.962,93.091 ; 19.279,95.631 22.962,95.631 22.962,98.552 ; 22.962,90.551 22.962,88.621 22.987,88.595 ; 23.317,90.551 19.279,90.551 ; 25.806,85.141 40.843,85.141 ; 25.806,88.595 22.987,88.595 ; 25.806,90.551 25.806,83.464 40.843,83.464 40.843,90.551 ; 30.607,95.656 30.607,98.552 ; 35.687,83.49 35.687,90.551 ; 38.176,95.707 38.176,98.527 ; 40.945,87.859 43.383,87.859 ; 43.383,85.166 53.543,85.166 ; 43.383,90.551 43.383,83.464 53.569,83.464 53.569,90.551 ; 48.336,95.656 48.336,98.45 ; 53.569,95.631 53.569,98.552 30.607,98.552 ; 19.279,90.551 19.279,88.541 19.332,88.595 22.987,88.595 ; 19.279,90.551 19.279,98.552 22.962,98.552 ; 22.962,98.552 30.607,98.552 ; 24.206,1.168 65.642,1.168 67.01,2.536 67.01,10.736 24.206,10.736 24.206,1.168
  text "PORST" at 19.583,96.723 h0.7
  text "3.3V" at 52.553,96.088 h0.8 r90
  text "5V" at 47.549,96.063 h0.8 r90
  text "TX0" at 34.747,96.037 h0.8 r90
  text "TX1" at 27.102,95.987 h0.8 r90
  text "GND" at 32.258,95.987 h0.8 r90
  text "GND" at 50.013,95.987 h0.8 r90
  text "GND" at 24.587,95.961 h0.8 r90
  text "RX1" at 29.718,95.961 h0.8 r90
  text "RX0" at 37.236,95.961 h0.8 r90
  text "GND" at 39.878,95.961 h0.8 r90
  text "DP" at 42.393,95.961 h0.8 r90
  text "DM" at 44.958,95.961 h0.8 r90
  text "GND" at 20.015,89.154 h0.8
  text "VIN" at 23.419,89.154 h0.8
  text "WS" at 32.309,88.584 h0.8 r90
  text "SDI" at 27.178,88.371 h0.8 r90
  text "CS1" at 42.418,88.363 h0.8 r90
  text "CS0" at 44.983,88.173 h0.8 r90
  text "SDO" at 29.769,88.028 h0.8 r90
  text "MOSI" at 52.68,87.514 h0.8 r90
  text "MISO" at 50.013,87.48 h0.8 r90
  text "I2SCLK" at 34.874,86.234 h0.8 r90
  text "I2CCLK" at 37.389,86.2 h0.8 r90
  text "SPICLK" at 47.473,86.131 h0.8 r90
  text "I2CDATE" at 39.853,85.457 h0.8 r90
  text "FLASH" at 46.558,83.947 h0.8
  text "I2C" at 37.389,83.922 h0.8
  text "I2S" at 30.048,83.896 h0.8
  text "GPIO0" at 14.58,79.654 h0.8
  text "GND" at 52.9,79.625 h0.8
  text "GND" at 15.49,77.646 h0.8
  text "+3.3V" at 52.9,77.625 h0.8
  text "CS0" at 15.845,75.717 h0.8
  text "+3.3V" at 52.9,75.625 h0.8
  text "REF_CLK" at 12.603,73.913 h0.8
  text "DM" at 52.9,73.625 h0.8
  text "WDT_RST" at 12.584,71.913 h0.8
  text "DP" at 52.9,71.625 h0.8
  text "PORT_N" at 13.289,69.913 h0.8
  text "GND" at 52.9,69.625 h0.8
  text "LINK4" at 14.397,67.646 h0.8
  text "TXON4" at 52.9,67.625 h0.8
  text "+" at 24.5,65.72 h0.8
  text "LINK3" at 14.473,65.646 h0.8
  text "TXOP4" at 52.9,65.625 h0.8
  text "LINK2" at 14.473,63.646 h0.8
  text "RXIN4" at 52.9,63.625 h0.8
  text "RESTART" at 4.5,62.15 h1
  text "LINK1" at 14.664,61.646 h0.8
  text "RXIP4" at 52.9,61.625 h0.8
  text "LINK0" at 14.473,59.646 h0.8
  text "RXIN3" at 52.9,59.625 h0.8
  text "+" at 43.164,58 h0.8
  text "WIFI_LED" at 12.44,57.913 h0.8
  text "RXIP3" at 52.9,57.625 h0.8
  text "J6" at 48.463,56.617 h0.8
  text "J5" at 21.387,56.49 h0.8
  text "TX1" at 15.932,55.646 h0.8
  text "TXON3" at 52.9,55.625 h0.8
  text "RX1" at 15.829,53.646 h0.8
  text "TXOP3" at 52.9,53.625 h0.8
  text "SDI" at 16.077,51.646 h0.8
  text "TXON2" at 52.9,51.625 h0.8
  text "SDO" at 15.734,49.646 h0.8
  text "TXOP2" at 52.9,49.625 h0.8
  text "WS" at 16.29,47.646 h0.8
  text "RXIN2" at 52.9,47.625 h0.8
  text "I2SCLK" at 13.94,45.646 h0.8
  text "RXIP2" at 52.9,45.625 h0.8
  text "I2CCLK" at 13.906,43.646 h0.8
  text "RXIN1" at 52.9,43.625 h0.8
  text "I2CDATE" at 13.163,41.646 h0.8
  text "RXIP1" at 52.9,41.625 h0.8
  text "CS1" at 16.069,39.646 h0.8
  text "TXON1" at 52.9,39.625 h0.8
  text "SPICLK" at 13.837,37.646 h0.8
  text "TXOP1" at 52.9,37.625 h0.8
  text "MISO" at 15.186,35.646 h0.8
  text "TXON0" at 52.9,35.625 h0.8
  text "MOSI" at 15.22,33.646 h0.8
  text "TXOP0" at 52.9,33.625 h0.8
  text "TX0" at 15.742,31.646 h0.8
  text "RXIN0" at 52.9,31.625 h0.8
  text "RX0" at 15.656,29.685 h0.8
  text "RXIP0" at 52.9,29.625 h0.8
  text "RESET" at 4.547,20.295 h1
  text "WIFI_LED2" at 6.477,15.392 h1
  text "HLK-RM08A-KIT-V2.5" at 30.455,13.716 h2
  text "RESET" at 49.21,3.736 h1.52
  text "RESTART" at 59.21,3.736 h1.52
  text "ES0/Default" at 24.613,1.981 h2
  text "VIN:5V-16V" at 16.18,1.956 h1.52 r90
  text "保留" at 38.51,1.949 h2
  text "恢复出厂设置" at 46.61,1.951 h2
  text "重启模块" at 58.71,1.947 h2
Bottom Overlay:
  text "GND" at 13.202,86.265 h0.8
  text "RX1_232" at 16.202,80.765 h0.8
  text "TX1_232" at 16.202,77.765 h0.8
  text "GND" at 13.487,44.069 h0.8
  text "RX0_232" at 16.126,38.551 h0.8
  text "TX0_232" at 16.126,36.051 h0.8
